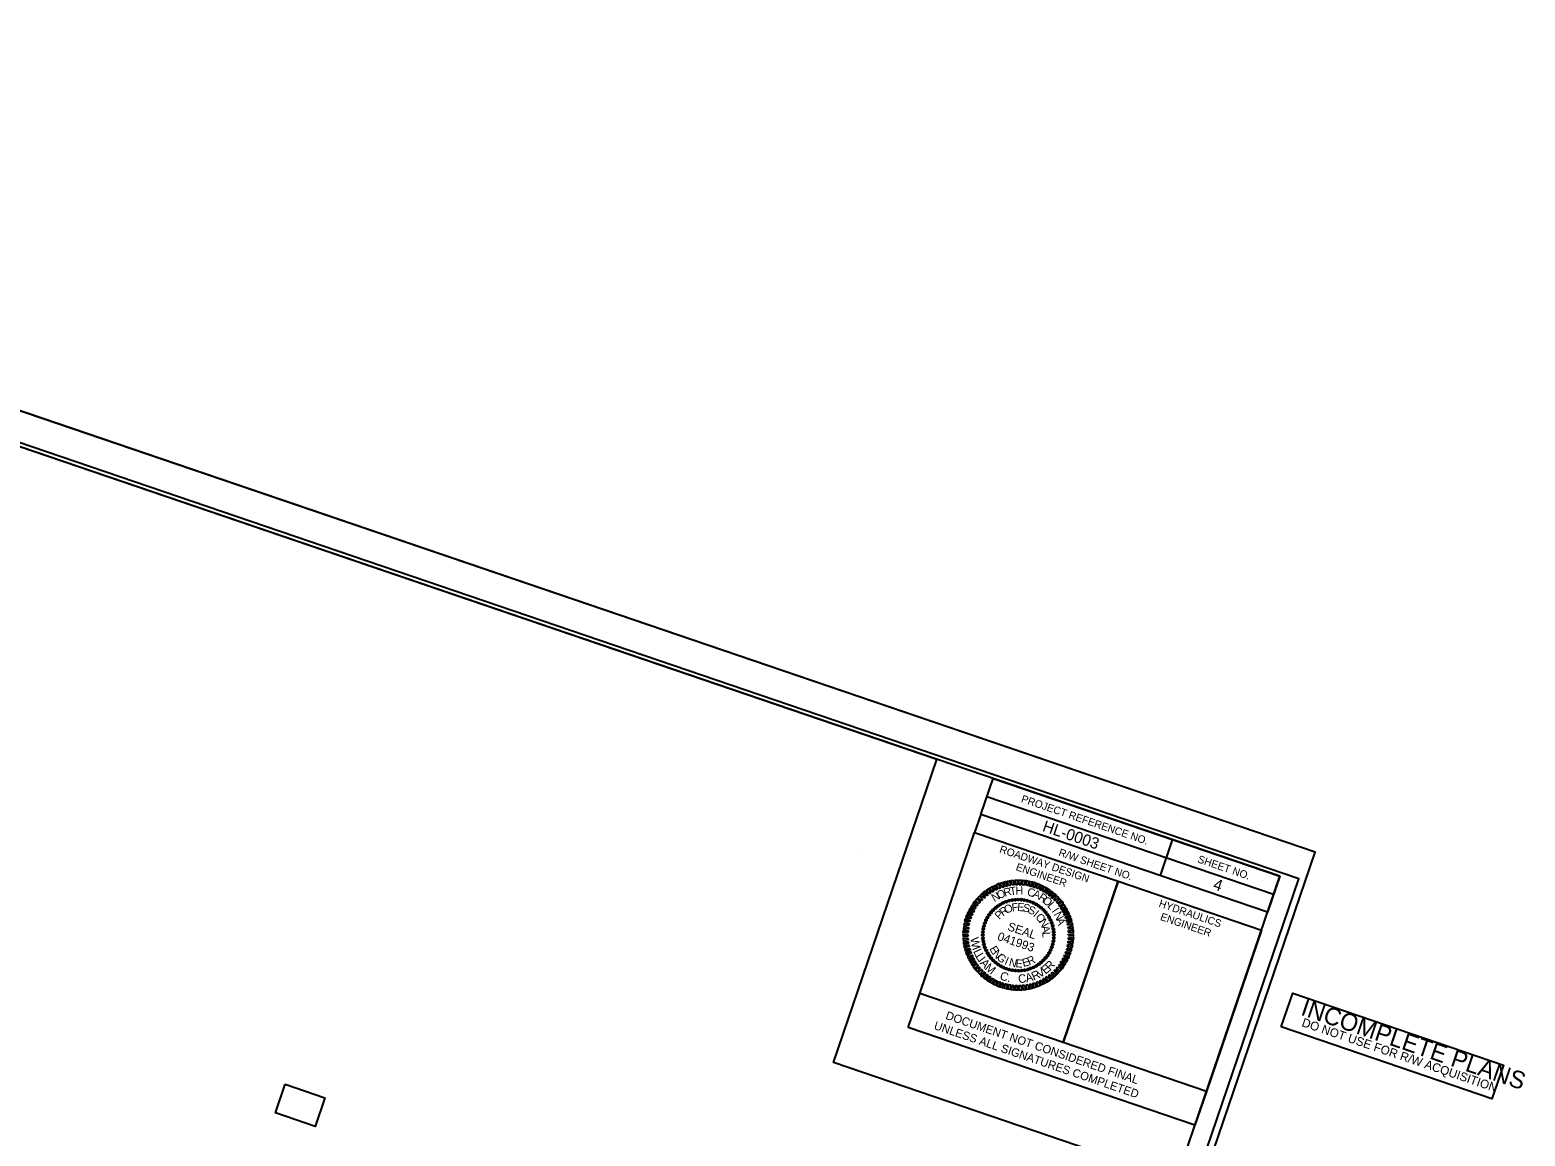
# Model space of a CAD drawing. Extents: x 927646 to 937215, y 684320 to 686920.
# Drawn here: x 928744 to 929731, y 686190 to 686920 of the extents above; entities that cross this region are included whole.
import ezdxf

# ---------------------------------------------------------------- set-up
doc = ezdxf.new("R2010")
doc.units = 0
for name, color, linetype in [('Default', 7, 'Continuous'), ('Exist Horizontal Alignment Station Label', 7, 'Continuous'), ('Sheet Cutting Line CELL', 7, 'Continuous'), ('Sheet Data Field CELL', 7, 'Continuous'), ('Sheet North Arrow Point CELL', 7, 'Continuous'), ('Sheet Plan CELL', 7, 'Continuous'), ('Sheet Plan Layout CELL', 7, 'Continuous'), ('Sheet Plot Border Inside CELL', 7, 'Continuous'), ('Sheet Plot Border Outside CELL', 7, 'Continuous'), ('Sheet Sticker Exception Certification CELL', 7, 'Continuous')]:
    doc.layers.add(name, color=color, linetype=linetype)

msp = doc.modelspace()

# ---------------------------------------------------------------- linework, layer by layer
at = {"layer": 'Default'}
for p, q in [((929388.4, 686344.79), (929388.4, 686344.79)), ((929390.33, 686345.37), (929390.33, 686345.37)), ((929392.36, 686345.82), (929392.36, 686345.82)), ((929394.39, 686346.12), (929394.39, 686346.12)), ((929396.41, 686346.22), (929396.41, 686346.22)), ((929398.46, 686346.12), (929398.46, 686346.12)), ((929400.53, 686345.81), (929400.53, 686345.81)), ((929402.53, 686345.43), (929402.53, 686345.43)), ((929404.5, 686344.81), (929404.5, 686344.81)), ((929376.13, 686334.37), (929376.13, 686334.37)), ((929377.16, 686336.09), (929377.16, 686336.09)), ((929378.42, 686337.75), (929378.42, 686337.75)), ((929379.82, 686339.25), (929379.82, 686339.25)), ((929381.3, 686340.68), (929381.3, 686340.68)), ((929382.95, 686341.9), (929382.95, 686341.9)), ((929384.68, 686343.04), (929384.68, 686343.04)), ((929386.48, 686343.96), (929386.48, 686343.96)), ((929406.4, 686344.01), (929406.4, 686344.01)), ((929408.2, 686343.05), (929408.2, 686343.05)), ((929409.93, 686342.01), (929409.93, 686342.01)), ((929411.58, 686340.76), (929411.58, 686340.76)), ((929413.09, 686339.35), (929413.09, 686339.35)), ((929414.51, 686337.88), (929414.51, 686337.88)), ((929415.73, 686336.22), (929415.73, 686336.22)), ((929416.88, 686334.5), (929416.88, 686334.5)), ((929373.05, 686324.62), (929373.05, 686324.62)), ((929373.36, 686326.69), (929373.36, 686326.69)), ((929373.75, 686328.69), (929373.75, 686328.69)), ((929374.37, 686330.66), (929374.37, 686330.66)), ((929375.17, 686332.56), (929375.17, 686332.56)), ((929417.8, 686332.7), (929417.8, 686332.7)), ((929418.63, 686330.78), (929418.63, 686330.78)), ((929419.21, 686328.85), (929419.21, 686328.85)), ((929419.66, 686326.81), (929419.66, 686326.81)), ((929419.96, 686324.78), (929419.96, 686324.78)), ((929372.95, 686322.57), (929372.95, 686322.57)), ((929373.06, 686320.56), (929373.06, 686320.56)), ((929373.35, 686318.52), (929373.35, 686318.52)), ((929373.8, 686316.49), (929373.8, 686316.49)), ((929374.38, 686314.56), (929374.38, 686314.56)), ((929396.51, 686322.67), (929396.51, 686322.67)), ((929418.64, 686314.68), (929418.64, 686314.68)), ((929419.26, 686316.65), (929419.26, 686316.65)), ((929419.65, 686318.65), (929419.65, 686318.65)), ((929419.96, 686320.72), (929419.96, 686320.72)), ((929420.06, 686322.76), (929420.06, 686322.76)), ((929375.21, 686312.64), (929375.21, 686312.64)), ((929376.13, 686310.84), (929376.13, 686310.84)), ((929377.28, 686309.11), (929377.28, 686309.11)), ((929378.5, 686307.46), (929378.5, 686307.46)), ((929379.93, 686305.98), (929379.93, 686305.98)), ((929411.71, 686304.66), (929411.71, 686304.66)), ((929413.19, 686306.09), (929413.19, 686306.09)), ((929414.59, 686307.59), (929414.59, 686307.59)), ((929415.85, 686309.24), (929415.85, 686309.24)), ((929416.89, 686310.97), (929416.89, 686310.97)), ((929417.85, 686312.77), (929417.85, 686312.77)), ((929381.43, 686304.58), (929381.43, 686304.58)), ((929383.08, 686303.32), (929383.08, 686303.32)), ((929384.81, 686302.29), (929384.81, 686302.29)), ((929386.61, 686301.33), (929386.61, 686301.33)), ((929388.52, 686300.53), (929388.52, 686300.53)), ((929390.48, 686299.91), (929390.48, 686299.91)), ((929392.48, 686299.53), (929392.48, 686299.53)), ((929394.56, 686299.22), (929394.56, 686299.22)), ((929396.6, 686299.11), (929396.6, 686299.11)), ((929398.62, 686299.22), (929398.62, 686299.22)), ((929400.65, 686299.52), (929400.65, 686299.52)), ((929402.68, 686299.96), (929402.68, 686299.96)), ((929404.62, 686300.54), (929404.62, 686300.54)), ((929406.53, 686301.37), (929406.53, 686301.37)), ((929408.33, 686302.3), (929408.33, 686302.3)), ((929410.06, 686303.44), (929410.06, 686303.44))]:
    msp.add_line(p, q, dxfattribs=at)
for points in [[(929379.26, 686351.13), (929377.55, 686353.64), (929378.92, 686354.46), (929380.16, 686351.71)], [(929381.39, 686352.28), (929379.75, 686354.87), (929381.2, 686355.52), (929382.34, 686352.75)], [(929383.38, 686353.34), (929382.1, 686355.95), (929383.53, 686356.66), (929384.44, 686353.67)], [(929385.63, 686354.11), (929384.45, 686356.89), (929385.96, 686357.41), (929386.67, 686354.4)], [(929387.77, 686354.86), (929386.9, 686357.69), (929388.34, 686358.14), (929388.93, 686355.06)], [(929390.1, 686355.31), (929389.27, 686358.26), (929390.89, 686358.5), (929391.12, 686355.55)], [(929392.37, 686355.72), (929391.8, 686358.69), (929393.38, 686358.84), (929393.48, 686355.79)], [(929394.64, 686355.99), (929394.36, 686358.96), (929395.87, 686359.03), (929395.84, 686355.88)], [(929397.05, 686355.96), (929396.94, 686358.97), (929398.45, 686358.9), (929398.09, 686355.95)], [(929399.38, 686355.81), (929399.4, 686358.92), (929401.02, 686358.72), (929400.39, 686355.71)], [(929401.68, 686355.57), (929401.93, 686358.65), (929403.44, 686358.29), (929402.79, 686355.34)], [(929403.9, 686355.11), (929404.38, 686358.12), (929405.95, 686357.78), (929405.01, 686354.88)], [(929406.19, 686354.58), (929406.95, 686357.54), (929408.4, 686356.99), (929407.24, 686354.17)], [(929408.31, 686353.81), (929409.29, 686356.69), (929410.74, 686356.15), (929409.36, 686353.4)], [(929410.48, 686352.92), (929411.64, 686355.74), (929413.01, 686354.98), (929411.48, 686352.38)], [(929412.49, 686351.84), (929413.85, 686354.54), (929415.24, 686353.82), (929413.51, 686351.34)], [(929369.18, 686341.74), (929366.63, 686343.25), (929367.44, 686344.61), (929369.85, 686342.55)], [(929370.57, 686343.64), (929368.09, 686345.37), (929369.14, 686346.55), (929371.38, 686344.4)], [(929372.12, 686345.29), (929369.72, 686347.25), (929370.86, 686348.4), (929372.9, 686346.11)], [(929373.71, 686347.03), (929371.56, 686349), (929372.69, 686350.15), (929374.53, 686347.69)], [(929375.42, 686348.57), (929373.39, 686350.75), (929374.7, 686351.69), (929376.4, 686349.13)], [(929377.36, 686349.89), (929375.48, 686352.22), (929376.76, 686353.22), (929378.22, 686350.54)], [(929414.58, 686350.58), (929416.01, 686353.31), (929417.4, 686352.44), (929415.44, 686350.04)], [(929416.52, 686349.28), (929418.12, 686351.8), (929419.34, 686350.89), (929417.34, 686348.65)], [(929418.24, 686347.8), (929420.22, 686350.25), (929421.28, 686349.29), (929419.16, 686347.14)], [(929419.95, 686346.27), (929421.95, 686348.51), (929423.12, 686347.42), (929420.76, 686345.45)], [(929421.64, 686344.56), (929423.7, 686346.68), (929424.78, 686345.47), (929422.31, 686343.74)], [(929422.97, 686342.77), (929425.4, 686344.82), (929426.23, 686343.49), (929423.76, 686341.91)], [(929365, 686333.4), (929362.07, 686334.25), (929362.59, 686335.76), (929365.37, 686334.47)], [(929365.8, 686335.61), (929362.95, 686336.68), (929363.54, 686338.11), (929366.26, 686336.64)], [(929366.75, 686337.66), (929364, 686338.89), (929364.69, 686340.34), (929367.34, 686338.65)], [(929367.88, 686339.8), (929365.25, 686341.09), (929366.07, 686342.5), (929368.55, 686340.61)], [(929424.33, 686340.82), (929426.81, 686342.7), (929427.63, 686341.33), (929424.96, 686339.91)], [(929425.55, 686338.87), (929428.16, 686340.56), (929428.86, 686339.13), (929426.17, 686337.92)], [(929426.62, 686336.77), (929429.24, 686338.21), (929429.94, 686336.78), (929427.04, 686335.84)], [(929427.63, 686334.65), (929430.35, 686335.95), (929430.87, 686334.43), (929427.95, 686333.55)], [(929363.31, 686324.37), (929360.13, 686324.32), (929360.36, 686325.87), (929363.32, 686325.41)], [(929363.51, 686326.68), (929360.42, 686326.79), (929360.67, 686328.39), (929363.56, 686327.71)], [(929363.83, 686328.95), (929360.74, 686329.31), (929361.12, 686330.86), (929364.02, 686330.07)], [(929364.29, 686331.17), (929361.29, 686331.8), (929361.71, 686333.34), (929364.57, 686332.26)], [(929428.37, 686332.46), (929431.18, 686333.58), (929431.58, 686332.01), (929428.61, 686331.44)], [(929428.9, 686330.25), (929431.83, 686331.13), (929432.22, 686329.52), (929429.22, 686329.15)], [(929429.39, 686327.9), (929432.4, 686328.61), (929432.51, 686327.04), (929429.64, 686326.88)], [(929429.63, 686325.69), (929432.7, 686326.13), (929432.79, 686324.52), (929429.74, 686324.57)], [(929363.3, 686322), (929360.2, 686321.77), (929360.18, 686323.31), (929363.17, 686323.08)], [(929363.39, 686319.64), (929360.31, 686319.2), (929360.22, 686320.82), (929363.27, 686320.77)], [(929363.62, 686317.43), (929360.61, 686316.73), (929360.5, 686318.3), (929363.38, 686318.46)], [(929364.11, 686315.09), (929361.19, 686314.2), (929360.8, 686315.82), (929363.79, 686316.19)], [(929429.18, 686316.39), (929432.28, 686316.03), (929431.89, 686314.47), (929428.99, 686315.26)], [(929429.51, 686318.65), (929432.59, 686318.54), (929432.34, 686316.95), (929429.46, 686317.63)], [(929429.7, 686320.97), (929432.89, 686321.02), (929432.65, 686319.46), (929429.69, 686319.93)], [(929429.72, 686323.34), (929432.82, 686323.57), (929432.83, 686322.03), (929429.84, 686322.25)], [(929364.64, 686312.87), (929361.84, 686311.75), (929361.43, 686313.33), (929364.4, 686313.9)], [(929365.39, 686310.69), (929362.66, 686309.39), (929362.14, 686310.91), (929365.07, 686311.79)], [(929366.4, 686308.56), (929363.78, 686307.13), (929363.07, 686308.56), (929365.97, 686309.5)], [(929367.46, 686306.47), (929364.86, 686304.78), (929364.16, 686306.21), (929366.85, 686307.42)], [(929368.68, 686304.52), (929366.21, 686302.64), (929365.39, 686304.01), (929368.05, 686305.43)], [(929425.14, 686305.53), (929427.77, 686304.24), (929426.94, 686302.84), (929424.46, 686304.72)], [(929426.26, 686307.68), (929429.01, 686306.44), (929428.32, 686304.99), (929425.68, 686306.69)], [(929427.21, 686309.73), (929430.06, 686308.66), (929429.47, 686307.23), (929426.76, 686308.7)], [(929428.01, 686311.93), (929430.94, 686311.08), (929430.42, 686309.58), (929427.65, 686310.87)], [(929428.72, 686314.17), (929431.73, 686313.54), (929431.3, 686312), (929428.45, 686313.07)], [(929370.05, 686302.57), (929367.62, 686300.52), (929366.78, 686301.85), (929369.25, 686303.43)], [(929371.37, 686300.78), (929369.31, 686298.66), (929368.23, 686299.87), (929370.71, 686301.6)], [(929373.06, 686299.06), (929371.06, 686296.82), (929369.9, 686297.91), (929372.25, 686299.88)], [(929374.77, 686297.54), (929372.8, 686295.09), (929371.74, 686296.05), (929373.86, 686298.2)], [(929376.5, 686296.06), (929374.89, 686293.54), (929373.67, 686294.45), (929375.67, 686296.69)], [(929378.43, 686294.76), (929377, 686292.02), (929375.61, 686292.89), (929377.57, 686295.3)], [(929415.66, 686295.44), (929417.54, 686293.12), (929416.26, 686292.12), (929414.79, 686294.8)], [(929417.59, 686296.76), (929419.62, 686294.59), (929418.31, 686293.65), (929416.61, 686296.21)], [(929419.31, 686298.31), (929421.46, 686296.34), (929420.32, 686295.19), (929418.49, 686297.65)], [(929420.89, 686300.05), (929423.29, 686298.09), (929422.16, 686296.94), (929420.11, 686299.22)], [(929422.44, 686301.7), (929424.92, 686299.96), (929423.87, 686298.78), (929421.64, 686300.93)], [(929423.83, 686303.6), (929426.39, 686302.09), (929425.58, 686300.73), (929423.16, 686302.79)], [(929380.53, 686293.5), (929379.16, 686290.79), (929377.77, 686291.52), (929379.51, 686293.99)], [(929382.53, 686292.42), (929381.37, 686289.59), (929380, 686290.36), (929381.53, 686292.96)], [(929384.71, 686291.53), (929383.72, 686288.64), (929382.28, 686289.19), (929383.66, 686291.94)], [(929386.82, 686290.76), (929386.06, 686287.8), (929384.61, 686288.34), (929385.77, 686291.17)], [(929389.12, 686290.22), (929388.64, 686287.22), (929387.07, 686287.56), (929388.01, 686290.45)], [(929391.34, 686289.77), (929391.08, 686286.68), (929389.57, 686287.05), (929390.23, 686289.99)], [(929393.63, 686289.53), (929393.61, 686286.41), (929392, 686286.62), (929392.63, 686289.62)], [(929395.96, 686289.38), (929396.07, 686286.37), (929394.56, 686286.44), (929394.92, 686289.39)], [(929398.37, 686289.35), (929398.65, 686286.38), (929397.14, 686286.3), (929397.17, 686289.46)], [(929400.64, 686289.61), (929401.22, 686286.65), (929399.63, 686286.49), (929399.53, 686289.55)], [(929402.92, 686290.03), (929403.74, 686287.07), (929402.12, 686286.83), (929401.89, 686289.78)], [(929405.25, 686290.47), (929406.12, 686287.65), (929404.68, 686287.2), (929404.09, 686290.27)], [(929407.39, 686291.23), (929408.57, 686288.45), (929407.05, 686287.93), (929406.35, 686290.94)], [(929409.63, 686292), (929410.92, 686289.38), (929409.49, 686288.68), (929408.57, 686291.67)], [(929411.62, 686293.05), (929413.27, 686290.46), (929411.81, 686289.82), (929410.67, 686292.59)], [(929413.75, 686294.21), (929415.47, 686291.69), (929414.1, 686290.87), (929412.86, 686293.62)]]:
    msp.add_lwpolyline(points, close=True, dxfattribs=at)
for centre, major_axis in [((929386.5, 686343.95), (-0.287, 0.611)), ((929388.39, 686344.74), (-0.233, 0.634)), ((929390.35, 686345.36), (-0.177, 0.651)), ((929392.35, 686345.81), (-0.119, 0.664)), ((929394.38, 686346.08), (-0.061, 0.672)), ((929396.43, 686346.18), (-0.002, 0.675)), ((929398.48, 686346.1), (0.057, 0.673)), ((929400.52, 686345.84), (0.115, 0.665)), ((929402.52, 686345.4), (0.173, 0.653)), ((929404.48, 686344.79), (0.229, 0.635)), ((929406.37, 686344.01), (0.283, 0.613)), ((929376.11, 686334.36), (-0.586, 0.336)), ((929377.2, 686336.09), (-0.554, 0.385)), ((929378.45, 686337.72), (-0.518, 0.432)), ((929379.83, 686339.24), (-0.479, 0.476)), ((929381.34, 686340.63), (-0.436, 0.516)), ((929382.96, 686341.89), (-0.389, 0.552)), ((929384.69, 686342.99), (-0.339, 0.583)), ((929408.2, 686343.07), (0.336, 0.586)), ((929409.93, 686341.97), (0.385, 0.554)), ((929411.56, 686340.73), (0.432, 0.518)), ((929413.08, 686339.35), (0.476, 0.479)), ((929414.47, 686337.84), (0.516, 0.436)), ((929415.72, 686336.22), (0.552, 0.389)), ((929416.83, 686334.49), (0.583, 0.339)), ((929373.08, 686324.64), (-0.673, 0.057)), ((929373.34, 686326.68), (-0.665, 0.115)), ((929373.78, 686328.68), (-0.653, 0.173)), ((929374.39, 686330.64), (-0.635, 0.229)), ((929375.17, 686332.54), (-0.613, 0.283)), ((929417.78, 686332.67), (0.611, 0.287)), ((929418.58, 686330.78), (0.634, 0.233)), ((929419.2, 686328.83), (0.651, 0.177)), ((929419.65, 686326.83), (0.664, 0.119)), ((929419.92, 686324.79), (0.672, 0.061)), ((929372.99, 686322.59), (-0.675, -0.002)), ((929373.09, 686320.54), (-0.672, -0.061)), ((929373.36, 686318.51), (-0.664, -0.119)), ((929373.81, 686316.51), (-0.651, -0.177)), ((929374.44, 686314.56), (-0.634, -0.233)), ((929418.63, 686314.7), (0.635, -0.229)), ((929419.24, 686316.66), (0.653, -0.173)), ((929419.67, 686318.66), (0.665, -0.115)), ((929419.94, 686320.69), (0.673, -0.057)), ((929420.02, 686322.74), (0.675, 0.002)), ((929375.23, 686312.66), (-0.611, -0.287)), ((929376.18, 686310.85), (-0.583, -0.339)), ((929377.29, 686309.12), (-0.552, -0.389)), ((929378.54, 686307.5), (-0.516, -0.436)), ((929379.93, 686305.99), (-0.476, -0.479)), ((929381.45, 686304.61), (-0.432, -0.518)), ((929411.68, 686304.71), (0.436, -0.516)), ((929413.19, 686306.1), (0.479, -0.476)), ((929414.57, 686307.61), (0.518, -0.432)), ((929415.81, 686309.24), (0.554, -0.385)), ((929416.91, 686310.98), (0.586, -0.336)), ((929417.85, 686312.8), (0.613, -0.283)), ((929383.08, 686303.37), (-0.385, -0.554)), ((929384.82, 686302.27), (-0.336, -0.586)), ((929386.64, 686301.33), (-0.283, -0.613)), ((929388.54, 686300.55), (-0.229, -0.635)), ((929390.49, 686299.94), (-0.173, -0.653)), ((929392.5, 686299.5), (-0.115, -0.665)), ((929394.53, 686299.24), (-0.057, -0.673)), ((929396.58, 686299.16), (0.002, -0.675)), ((929398.63, 686299.25), (0.061, -0.672)), ((929400.66, 686299.53), (0.119, -0.664)), ((929402.66, 686299.98), (0.177, -0.651)), ((929404.62, 686300.6), (0.233, -0.634)), ((929406.51, 686301.39), (0.287, -0.611)), ((929408.33, 686302.34), (0.339, -0.583)), ((929410.05, 686303.45), (0.389, -0.552))]:
    msp.add_ellipse(centre, major_axis=major_axis, ratio=0.999708, dxfattribs=at)
at = {"layer": 'Exist Horizontal Alignment Station Label'}
msp.add_lwpolyline([(928912.38, 686224.2), (928938.56, 686215.28), (928932.14, 686196.43), (928905.96, 686205.35)], close=True, dxfattribs=at)
at = {"layer": 'Sheet Cutting Line CELL'}
msp.add_line((929592.49, 686377.36), (927998.96, 686920.35), dxfattribs=at)
at = {"layer": 'Sheet North Arrow Point CELL'}
msp.add_line((929291.83, 686379), (929291.83, 686379), dxfattribs=at)
at = {"layer": 'Sheet Plan CELL'}
for p, q in [((929375.73, 686414.22), (929565.09, 686349.68)), ((929371.7, 686402.34), (929367.67, 686390.52)), ((929498.1, 686385.7), (929490.08, 686362.02)), ((929323.82, 686261.8), (929331.4, 686284.04)), ((929513.17, 686197.28), (929323.82, 686261.8)), ((929520.75, 686219.51), (929513.17, 686197.27))]:
    msp.add_line(p, q, dxfattribs=at)
for points in [[(929569.17, 686361.55), (928149.3, 686845.36), (927810.64, 685851.48), (929230.48, 685367.67)], [(929379.79, 686426.09), (929569.17, 686361.55), (929561.06, 686337.85), (929371.7, 686402.34)], [(929367.67, 686390.52), (929462.38, 686358.25), (929426.09, 686251.75), (929331.4, 686284.04)], [(929462.38, 686358.25), (929557.02, 686326.02), (929520.75, 686219.51), (929426.09, 686251.75)], [(929570.17, 686262.1), (929577.75, 686284.34), (929716.89, 686236.93), (929709.31, 686214.69)]]:
    msp.add_lwpolyline(points, close=True, dxfattribs=at)
at = {"layer": 'Sheet Plan Layout CELL'}
msp.add_lwpolyline([(928149.27, 686845.35), (927810.64, 685851.48), (929230.47, 685367.67), (929500.92, 686161.37), (929274.46, 686238.54), (929342.67, 686438.73)], close=True, dxfattribs=at)
at = {"layer": 'Sheet Plot Border Inside CELL'}
msp.add_lwpolyline([(927664.54, 685898.61), (929241.5, 685361.28), (929581.78, 686359.88), (928004.82, 686897.22)], close=True, dxfattribs=at)
at = {"layer": 'Sheet Plot Border Outside CELL'}
msp.add_lwpolyline([(927645.78, 685883.87), (929239.31, 685340.88), (929592.49, 686377.36), (927998.96, 686920.35)], close=True, dxfattribs=at)
at = {"layer": 'Sheet Sticker Exception Certification CELL'}
msp.add_line((929520.75, 686219.51), (929513.17, 686197.27), dxfattribs=at)

# ---------------------------------------------------------------- texts
at = {"layer": 'Default'}
for s, height, rotation, p in [('R', 5.29, 16.20411, (929387.6, 686347.99)), ('T', 5.29, 9.00337, (929391.29, 686348.91)), ('H', 5.29, 1.80308, (929394.67, 686349.39)), ('N', 5.29, 30.6071, (929380.69, 686344.4)), ('O', 5.29, 23.40534, (929383.6, 686346.28)), ('C', 5.29, 347.40347, (929402.02, 686348.87)), ('A', 5.29, 340.20392, (929405.61, 686347.94)), ('R', 5.29, 325.8047, (929409.28, 686346.49)), ('O', 5.29, 318.60476, (929412.03, 686344.82)), ('L', 5.29, 311.40448, (929415.37, 686341.84)), ('P', 5.29, 44.58249, (929383.94, 686332.59)), ('R', 5.29, 35.22325, (929386.33, 686334.95)), ('O', 5.29, 25.86484, (929388.62, 686336.6)), ('F', 5.29, 7.15063, (929392.44, 686338.22)), ('E', 5.29, 357.79467, (929395.74, 686338.58)), ('S', 5.29, 348.43921, (929399.12, 686338.47)), ('S', 5.29, 339.084, (929402.33, 686337.42)), ('I', 5.29, 320.3732, (929405.93, 686335.5)), ('O', 5.29, 311.01708, (929407.49, 686334.28)), ('I', 5.29, 304.20374, (929418.24, 686338.49)), ('N', 5.29, 297.00251, (929419.68, 686336.46)), ('041993', 5.623, 341.1836, (929382.28, 686319.59)), ('SEAL', 5.623, 341.1836, (929388.95, 686326.08)), ('N', 5.29, 301.66021, (929409.86, 686331.49)), ('A', 5.29, 282.94387, (929411.6, 686328.32)), ('L', 5.29, 273.58445, (929412.29, 686324.67)), ('A', 5.29, 289.80075, (929421.4, 686332.95)), ('W', 5.62, 279.541, (929364.78, 686320.84)), ('I', 5.62, 292.07507, (929365.93, 686314)), ('E', 5.29, 299.46049, (929377.22, 686313.74)), ('L', 5.62, 295.87702, (929366.57, 686311.99)), ('L', 5.62, 302.15179, (929367.92, 686308.78)), ('I', 5.62, 308.42655, (929369.61, 686305.74)), ('A', 5.62, 312.2285, (929370.79, 686303.99)), ('N', 5.29, 308.81756, (929379.07, 686310.44)), ('G', 5.29, 318.17384, (929381.76, 686307.29)), ('I', 5.29, 336.8848, (929387, 686303.62)), ('N', 5.29, 346.23999, (929389.92, 686302.48)), ('E', 5.29, 355.59536, (929394.5, 686301.51)), ('E', 5.29, 14.30769, (929399.79, 686301.64)), ('R', 5.29, 23.66501, (929403.65, 686302.65)), ('R', 5.62, 47.88002, (929417.62, 686298.92)), ('M', 5.62, 321.06881, (929373.96, 686300.26)), ('C', 5.62, 342.79866, (929383.86, 686293.51)), ('C', 5.62, 6.61494, (929396.71, 686290.89)), ('A', 5.62, 16.19709, (929402, 686291.36)), ('R', 5.62, 25.0374, (929406.75, 686292.58)), ('V', 5.62, 32.51766, (929410.58, 686294.17)), ('E', 5.62, 40.77068, (929414.52, 686296.48)), ('.', 5.62, 352.38081, (929388.89, 686291.81))]:
    msp.add_text(s, height=height, rotation=rotation, dxfattribs=at).set_placement(p)
at = {"layer": 'Sheet Data Field CELL'}
msp.add_text('4', height=7.5, rotation=341.1836, dxfattribs=at).set_placement((929524.63, 686353.22))
at = {"layer": 'Sheet Plan CELL'}
for s, height, p in [('PROJECT REFERENCE NO.', 5.0001, (929397.99, 686410.67)), ('HL-0003', 7.5, (929411.94, 686391.55)), ('ROADWAY DESIGN', 5.0001, (929383.66, 686377.37)), ('R/W SHEET NO.', 5.0001, (929422.69, 686375.26)), ('SHEET NO.', 5, (929514.54, 686370.84)), ('ENGINEER', 5, (929394.47, 686365.72)), ('HYDRAULICS', 5, (929488.86, 686341.54)), ('ENGINEER', 5, (929489.86, 686332.79)), ('INCOMPLETE PLANS', 11.52, (929582.41, 686270.29)), ('UNLESS ALL SIGNATURES COMPLETED', 5.5, (929340.37, 686260.76)), ('DOCUMENT NOT CONSIDERED FINAL', 5.5, (929348.01, 686267.46)), ('DO NOT USE FOR R/W ACQUISITION', 5.76, (929583.25, 686262.66))]:
    msp.add_text(s, height=height, rotation=341.1836, dxfattribs=at).set_placement(p)

doc.saveas('drawing.dxf')
